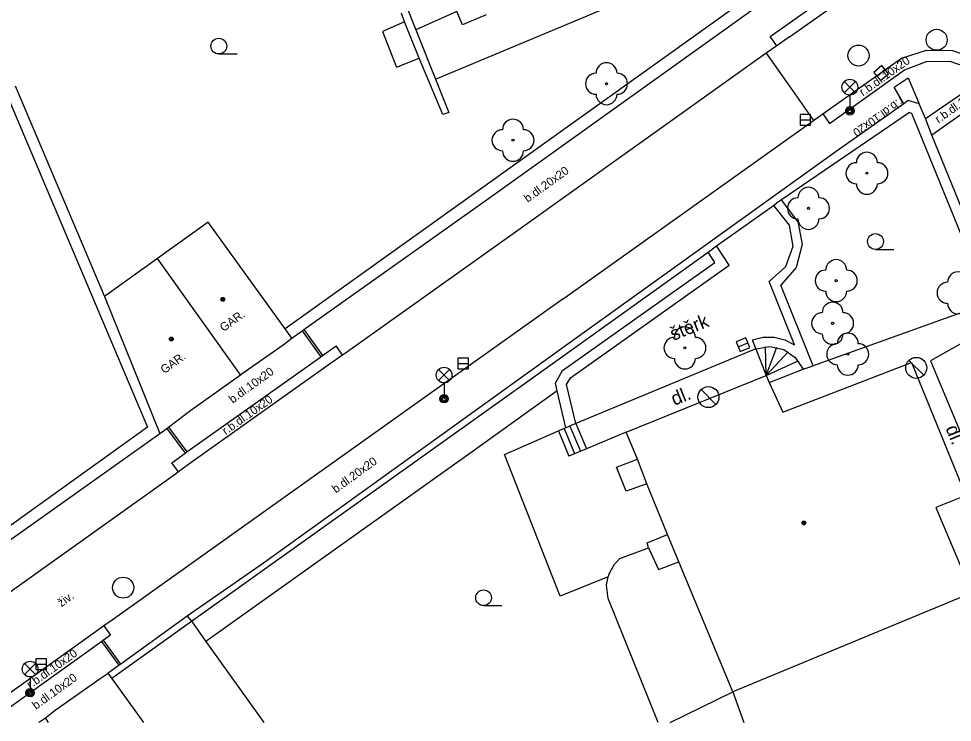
# Model space of a CAD drawing. Extents: x -600391 to -599491, y -1160176 to -1159402.
# Drawn here: x -599839.54 to -599795.12, y -1160176.08 to -1160142.59 of the extents above; entities that cross this region are included whole.
import ezdxf

# ---------------------------------------------------------------- set-up
doc = ezdxf.new("R2010")
doc.units = 0
for name, color, linetype in [('Level 10', 7, 'Continuous'), ('Level 11', 7, 'Continuous'), ('Level 22', 7, 'Continuous'), ('Level 27', 7, 'Continuous'), ('Level 33', 7, 'Continuous'), ('Level 36', 7, 'Continuous'), ('Level 39', 7, 'Continuous'), ('Level 40', 7, 'Continuous'), ('Level 41', 7, 'Continuous'), ('Level 5', 7, 'Continuous'), ('Level 51', 7, 'Continuous'), ('Level 6', 7, 'Continuous'), ('Level 7', 7, 'Continuous')]:
    doc.layers.add(name, color=color, linetype=linetype)

msp = doc.modelspace()

# ---------------------------------------------------------------- linework, layer by layer
at = {"layer": 'Level 10'}
for points in [[(-599802.86, -1160143.46), (-599798, -1160140.01)], [(-599802.86, -1160143.46), (-599803.47, -1160143.89), (-599803.97, -1160144.24), (-599815.9, -1160152.75), (-599823.99, -1160158.51), (-599824.13, -1160158.61), (-599824.81, -1160159.08), (-599831.29, -1160163.69), (-599831.93, -1160164.16), (-599832.08, -1160164.27), (-599845.83, -1160174.08), (-599846.15, -1160174.3), (-599846.65, -1160174.65), (-599848.652, -1160176.079)], [(-599797.53, -1160144.47), (-599796.35, -1160144.09), (-599795.11, -1160144.11), (-599793.94, -1160144.52)], [(-599813.64, -1160155.93), (-599801.72, -1160147.44), (-599801.28, -1160147.13), (-599797.53, -1160144.47)], [(-599813.64, -1160155.93), (-599829.07, -1160166.92), (-599835.1, -1160171.22), (-599835.49, -1160171.49), (-599835.91, -1160171.79), (-599841.925, -1160176.079)]]:
    msp.add_lwpolyline(points, dxfattribs=at)
at = {"layer": 'Level 11'}
msp.add_line((-599809.113, -1160176.079), (-599811.49, -1160170.18), dxfattribs=at)
for points in [[(-599819.71, -1160145.47), (-599802.47, -1160138.26), (-599804.18, -1160134.3)], [(-599803.78, -1160143.45), (-599798.3, -1160139.56)], [(-599817.3, -1160142.41), (-599818.43, -1160142.88), (-599818.7, -1160142.25), (-599820.65, -1160143.12)], [(-599803.47, -1160143.89), (-599803.78, -1160143.45)], [(-599803.97, -1160144.24), (-599802.83, -1160145.86), (-599801.72, -1160147.44)], [(-599797.39, -1160145.03), (-599796.35, -1160144.64), (-599795.24, -1160144.62), (-599794.19, -1160144.98)], [(-599800.96, -1160147.58), (-599797.39, -1160145.03)], [(-599797.43, -1160146.64), (-599797.88, -1160145.86), (-599797.21, -1160145.41), (-599796.7, -1160146.65)], [(-599796.39, -1160147.35), (-599793.96, -1160145.68), (-599793.34, -1160146.21), (-599796.09, -1160148.13)], [(-599801.28, -1160147.13), (-599800.96, -1160147.58)], [(-599793.38, -1160156.12), (-599801.74, -1160159.11)], [(-599826.05, -1160157.45), (-599825.17, -1160158.69)], [(-599825.97, -1160157.39), (-599825.09, -1160158.63)], [(-599792.97, -1160157.08), (-599796.15, -1160158.88)], [(-599832.25, -1160163.73), (-599831.62, -1160163.27), (-599831.54, -1160163.21), (-599825.17, -1160158.69), (-599825.09, -1160158.63), (-599824.44, -1160158.17)], [(-599824.13, -1160158.61), (-599824.44, -1160158.17)], [(-599804.47, -1160158.3), (-599813.03, -1160161.86), (-599813.5, -1160162.06), (-599813.86, -1160162.21)], [(-599804.47, -1160158.3), (-599803.98, -1160159.57)], [(-599803.98, -1160159.57), (-599804.01, -1160158.2)], [(-599803.98, -1160159.57), (-599803.47, -1160158.23)], [(-599803.98, -1160159.57), (-599802.93, -1160158.45)], [(-599803.98, -1160159.57), (-599802.45, -1160158.87)], [(-599803.83, -1160159.9), (-599802.21, -1160159.28)], [(-599796.15, -1160158.88), (-599793.65, -1160164.87)], [(-599813.03, -1160161.86), (-599812.53, -1160163.06)], [(-599832.5, -1160162.09), (-599831.62, -1160163.27)], [(-599832.42, -1160162.03), (-599831.54, -1160163.21)], [(-599811.49, -1160169.15), (-599813.78, -1160170.07), (-599816.42, -1160163.33), (-599813.86, -1160162.21)], [(-599813.86, -1160162.21), (-599813.36, -1160163.41)], [(-599813.58, -1160162.09), (-599813.09, -1160163.29)], [(-599810.63, -1160162.27), (-599812.53, -1160163.06), (-599813.36, -1160163.41)], [(-599813.31, -1160161.98), (-599812.81, -1160163.18)], [(-599831.93, -1160164.16), (-599832.25, -1160163.73)], [(-599809.65, -1160164.73), (-599810.63, -1160165.08), (-599811.09, -1160163.93), (-599810.09, -1160163.56)], [(-599809.57, -1160167.78), (-599809.64, -1160167.54), (-599808.67, -1160167.14)], [(-599810.93, -1160168.29), (-599809.57, -1160167.78)], [(-599809.57, -1160167.78), (-599809.09, -1160168.8), (-599808.13, -1160168.44)], [(-599811.49, -1160170.18), (-599811.57, -1160169.55), (-599811.49, -1160169.15), (-599811.42, -1160168.95), (-599811.19, -1160168.56), (-599810.93, -1160168.29)], [(-599835.49, -1160171.49), (-599835.18, -1160171.93)], [(-599835.18, -1160171.93), (-599835.5, -1160172.17), (-599835.58, -1160172.23), (-599840.98, -1160176.079)], [(-599834.68, -1160173.31), (-599835.5, -1160172.17)], [(-599834.76, -1160173.36), (-599835.58, -1160172.23)]]:
    msp.add_lwpolyline(points, dxfattribs=at)
at = {"layer": 'Level 22'}
for centre in [(-599811.57, -1160145.69), (-599816.02, -1160148.38), (-599799.18, -1160149.95), (-599801.96, -1160151.62), (-599800.64, -1160155.06), (-599800.81, -1160157.09), (-599807.84, -1160158.26), (-599800.09, -1160158.56)]:
    msp.add_circle(centre, 0.05, dxfattribs=at)
for centre, start, end in [((-599811.57, -1160145.19), 0, 180), ((-599812.07, -1160145.69), 90, 270), ((-599811.07, -1160145.69), 270, 90), ((-599811.57, -1160146.19), 180, 0), ((-599816.02, -1160147.88), 0, 180), ((-599816.52, -1160148.38), 90, 270), ((-599815.52, -1160148.38), 270, 90), ((-599816.02, -1160148.88), 180, 0), ((-599799.18, -1160149.45), 0, 180), ((-599799.68, -1160149.95), 90, 270), ((-599798.68, -1160149.95), 270, 90), ((-599801.96, -1160151.12), 0, 180), ((-599799.18, -1160150.45), 180, 0), ((-599802.46, -1160151.62), 90, 270), ((-599801.46, -1160151.62), 270, 90), ((-599801.96, -1160152.12), 180, 0), ((-599800.64, -1160154.56), 0, 180), ((-599801.14, -1160155.06), 90, 270), ((-599800.14, -1160155.06), 270, 90), ((-599794.84, -1160155.14), 0, 180), ((-599795.34, -1160155.64), 90, 270), ((-599800.64, -1160155.56), 180, 0), ((-599800.81, -1160156.59), 0, 180), ((-599794.84, -1160156.14), 180, 0), ((-599801.31, -1160157.09), 90, 270), ((-599800.31, -1160157.09), 270, 90), ((-599807.84, -1160157.76), 0, 180), ((-599808.34, -1160158.26), 90, 270), ((-599807.34, -1160158.26), 270, 90), ((-599800.81, -1160157.59), 180, 0), ((-599800.09, -1160158.06), 0, 180), ((-599800.59, -1160158.56), 90, 270), ((-599799.59, -1160158.56), 270, 90), ((-599807.84, -1160158.76), 180, 0), ((-599800.09, -1160159.06), 180, 0)]:
    msp.add_arc(centre, 0.5, start, end, dxfattribs=at)
at = {"layer": 'Level 27'}
for p, q in [((-599798.308, -1160145.02), (-599798.692, -1160145.34)), ((-599802.36, -1160147.41), (-599801.86, -1160147.41)), ((-599805.312, -1160158.204), (-599804.848, -1160158.016)), ((-599818.64, -1160159), (-599818.14, -1160159)), ((-599796.477, -1160159.564), (-599797.184, -1160158.857)), ((-599806.367, -1160160.954), (-599807.074, -1160160.247)), ((-599838.72, -1160173.31), (-599838.22, -1160173.31))]:
    msp.add_line(p, q, dxfattribs=at)
for points in [[(-599798.468, -1160144.828), (-599798.852, -1160145.148), (-599798.532, -1160145.532), (-599798.148, -1160145.212)], [(-599802.36, -1160147.66), (-599801.86, -1160147.66), (-599801.86, -1160147.16), (-599802.36, -1160147.16)], [(-599805.218, -1160158.436), (-599804.754, -1160158.248), (-599804.942, -1160157.784), (-599805.406, -1160157.972)], [(-599818.64, -1160159.25), (-599818.14, -1160159.25), (-599818.14, -1160158.75), (-599818.64, -1160158.75)], [(-599838.72, -1160173.56), (-599838.22, -1160173.56), (-599838.22, -1160173.06), (-599838.72, -1160173.06)]]:
    msp.add_lwpolyline(points, close=True, dxfattribs=at)
for centre in [(-599795.86, -1160143.6), (-599799.58, -1160144.35), (-599796.83, -1160159.21), (-599806.72, -1160160.6), (-599834.57, -1160169.67)]:
    msp.add_circle(centre, 0.5, dxfattribs=at)
at = {"layer": 'Level 33'}
for p, q in [((-599800.255, -1160146.12), (-599799.725, -1160145.59)), ((-599800.255, -1160145.59), (-599799.725, -1160146.12)), ((-599799.99, -1160146.23), (-599799.99, -1160146.98)), ((-599819.565, -1160159.82), (-599819.035, -1160159.29)), ((-599819.565, -1160159.29), (-599819.035, -1160159.82)), ((-599819.3, -1160159.93), (-599819.3, -1160160.68)), ((-599839.265, -1160173.81), (-599838.735, -1160173.28)), ((-599839.265, -1160173.28), (-599838.735, -1160173.81)), ((-599839, -1160173.92), (-599839, -1160174.67))]:
    msp.add_line(p, q, dxfattribs=at)
for centre, radius in [((-599799.99, -1160145.855), 0.375), ((-599799.99, -1160146.98), 0.2), ((-599799.99, -1160146.98), 0.145), ((-599799.99, -1160146.98), 0.0876), ((-599819.3, -1160159.555), 0.375), ((-599819.3, -1160160.68), 0.2), ((-599819.3, -1160160.68), 0.145), ((-599819.3, -1160160.68), 0.0876), ((-599839, -1160173.545), 0.375), ((-599839, -1160174.67), 0.2), ((-599839, -1160174.67), 0.145), ((-599839, -1160174.67), 0.0876)]:
    msp.add_circle(centre, radius, dxfattribs=at)
at = {"layer": 'Level 36'}
for p, q in [((-599830.02, -1160144.275), (-599829.145, -1160144.275)), ((-599798.77, -1160153.575), (-599797.895, -1160153.575)), ((-599817.42, -1160170.525), (-599816.545, -1160170.525))]:
    msp.add_line(p, q, dxfattribs=at)
for centre in [(-599830.02, -1160143.9), (-599798.77, -1160153.2), (-599817.42, -1160170.15)]:
    msp.add_circle(centre, 0.375, dxfattribs=at)
at = {"layer": 'Level 39'}
for centre, radius in [((-599829.83, -1160155.95), 0.09), ((-599829.83, -1160155.95), 0.0398), ((-599832.28, -1160157.84), 0.09), ((-599832.28, -1160157.84), 0.0398), ((-599802.18, -1160166.59), 0.09), ((-599802.18, -1160166.59), 0.0398)]:
    msp.add_circle(centre, radius, dxfattribs=at)
at = {"layer": 'Level 5'}
for p, q in [((-599808.543, -1160176.079), (-599805.56, -1160174.63)), ((-599805.56, -1160174.63), (-599805.032, -1160176.079)), ((-599838.116, -1160176.079), (-599838.27, -1160175.86))]:
    msp.add_line(p, q, dxfattribs=at)
for points in [[(-599830.52, -1160152.28), (-599832.93, -1160154.01)], [(-599826.54, -1160157.8), (-599826.86, -1160157.35), (-599830.52, -1160152.28)], [(-599832.93, -1160154.01), (-599835.46, -1160155.82)], [(-599828.98, -1160159.54), (-599832.93, -1160154.01)], [(-599835.46, -1160155.82), (-599832.83, -1160162.33)], [(-599826.96, -1160158.12), (-599826.54, -1160157.8)], [(-599803.18, -1160161.32), (-599797.05, -1160158.95)], [(-599797.05, -1160158.95), (-599794.5, -1160165.22), (-599794.47, -1160165.29)], [(-599829.43, -1160159.86), (-599828.98, -1160159.54)], [(-599828.98, -1160159.54), (-599828.9, -1160159.48)], [(-599810.63, -1160162.27), (-599803.98, -1160159.57)], [(-599803.98, -1160159.57), (-599803.83, -1160159.9), (-599803.18, -1160161.32)], [(-599832.83, -1160162.33), (-599832.5, -1160162.09), (-599832.42, -1160162.03), (-599831.35, -1160161.23)], [(-599810.09, -1160163.56), (-599810.63, -1160162.27)], [(-599809.65, -1160164.73), (-599810.09, -1160163.56)], [(-599808.67, -1160167.14), (-599809.65, -1160164.73)], [(-599794.47, -1160165.29), (-599795.9, -1160165.86)], [(-599795.9, -1160165.86), (-599794.3, -1160169.64), (-599794.18, -1160169.92)], [(-599808.13, -1160168.44), (-599808.67, -1160167.14)], [(-599805.56, -1160174.63), (-599808.13, -1160168.44)], [(-599794.18, -1160169.92), (-599805.56, -1160174.63)], [(-599835.66, -1160173.99), (-599835.28, -1160173.74)], [(-599833.583, -1160176.079), (-599835.11, -1160173.97), (-599835.28, -1160173.74)], [(-599838.27, -1160175.86), (-599837.8, -1160175.5)], [(-599838.55, -1160176.06), (-599838.27, -1160175.86)]]:
    msp.add_lwpolyline(points, dxfattribs=at)
at = {"layer": 'Level 51'}
for points in [[(-599821.11, -1160141.97), (-599820.65, -1160143.12), (-599819.71, -1160145.47), (-599819.07, -1160147.06)], [(-599821.19, -1160142.74), (-599821.33, -1160142.33)], [(-599821.19, -1160142.74), (-599822.23, -1160143.2)], [(-599820.48, -1160144.48), (-599821.19, -1160142.74)], [(-599822.23, -1160143.2), (-599821.57, -1160144.9)], [(-599821.57, -1160144.9), (-599820.48, -1160144.48)], [(-599819.36, -1160147.15), (-599820.48, -1160144.48)], [(-599819.07, -1160147.06), (-599819.36, -1160147.15)]]:
    msp.add_lwpolyline(points, dxfattribs=at)
at = {"layer": 'Level 6'}
msp.add_line((-599838.578, -1160176.079), (-599838.55, -1160176.06), dxfattribs=at)
for points in [[(-599828.9, -1160159.48), (-599826.96, -1160158.12)], [(-599831.35, -1160161.23), (-599829.43, -1160159.86)], [(-599837.8, -1160175.5), (-599835.66, -1160173.99)]]:
    msp.add_lwpolyline(points, dxfattribs=at)
at = {"layer": 'Level 7'}
for points in [[(-599800.63, -1160138.51), (-599800.86, -1160138.74), (-599826.86, -1160157.35)], [(-599817.08, -1160151.08), (-599800.58, -1160139.26)], [(-599839.71, -1160145.79), (-599835.46, -1160155.82)], [(-599840.19, -1160146.03), (-599833.42, -1160162.04), (-599847.39, -1160172.06)], [(-599792.92, -1160155.91), (-599796.09, -1160148.13), (-599796.39, -1160147.35), (-599796.7, -1160146.65), (-599797.22, -1160146.49), (-599797.43, -1160146.64), (-599800.65, -1160148.92), (-599812.5, -1160157.43), (-599827.9, -1160168.5), (-599831.52, -1160171.02)], [(-599797.16, -1160147.06), (-599803.24, -1160151.21), (-599803.48, -1160151.37)], [(-599797.16, -1160147.06), (-599797.06, -1160147.09), (-599793.38, -1160156.12)], [(-599826.54, -1160157.8), (-599826.05, -1160157.45), (-599825.97, -1160157.39), (-599817.08, -1160151.08)], [(-599802.47, -1160152.24), (-599803.24, -1160151.21)], [(-599814.26, -1160159.1), (-599806.74, -1160153.7), (-599806.33, -1160153.41), (-599803.63, -1160151.48), (-599803.48, -1160151.37)], [(-599803.63, -1160151.48), (-599802.88, -1160152.42), (-599802.71, -1160153.44), (-599803.06, -1160154.41), (-599803.83, -1160155.1)], [(-599802.47, -1160152.24), (-599802.26, -1160153.34), (-599802.54, -1160154.43), (-599803.27, -1160155.28)], [(-599813.03, -1160161.86), (-599813.47, -1160160.01), (-599813.29, -1160159.68), (-599805.73, -1160154.33), (-599806.33, -1160153.41)], [(-599813.5, -1160162.06), (-599813.92, -1160160.3), (-599814, -1160159.94), (-599813.67, -1160159.34), (-599806.41, -1160154.2), (-599806.74, -1160153.7)], [(-599802.63, -1160158.11), (-599803.83, -1160155.1)], [(-599801.74, -1160159.11), (-599803.27, -1160155.28)], [(-599804.63, -1160157.88), (-599804.12, -1160157.75), (-599803.6, -1160157.75), (-599803.09, -1160157.87)], [(-599804.47, -1160158.3), (-599804.63, -1160157.88)], [(-599803.09, -1160157.87), (-599802.63, -1160158.11)], [(-599804.47, -1160158.3), (-599803.8, -1160158.19), (-599803.14, -1160158.33), (-599802.59, -1160158.72)], [(-599802.59, -1160158.72), (-599802.21, -1160159.28)], [(-599831.32, -1160171.27), (-599814.26, -1160159.1)], [(-599802.21, -1160159.28), (-599801.74, -1160159.11)], [(-599813.92, -1160160.3), (-599817.96, -1160163.2), (-599830.63, -1160172.23)], [(-599847.1, -1160172.47), (-599832.83, -1160162.33)], [(-599831.52, -1160171.02), (-599834.68, -1160173.31), (-599834.76, -1160173.36), (-599835.28, -1160173.74)], [(-599835.11, -1160173.97), (-599831.32, -1160171.27)], [(-599831.52, -1160171.02), (-599831.32, -1160171.27)], [(-599831.32, -1160171.27), (-599830.63, -1160172.23), (-599827.874, -1160176.079)]]:
    msp.add_lwpolyline(points, dxfattribs=at)

# ---------------------------------------------------------------- texts
at = {"layer": 'Level 40'}
for s, height, rotation, p in [('r.b.dl.10x20', 0.39997, 35.3645, (-599799.37, -1160146.3)), ('r.b.dl.10x20', 0.4, 35.43, (-599795.77, -1160147.59)), ('r.b.dl.10x20', 0.4, 215, (-599797.6, -1160146.31)), ('b.dl.20x20', 0.4, 35.922, (-599815.32, -1160151.36)), ('štěrk', 0.65, 22, (-599808.39, -1160157.93)), ('b.dl.10x20', 0.4, 35.922, (-599829.36, -1160160.92)), ('dl.', 0.65, 22.0979, (-599808.34, -1160161.02)), ('r.b.dl.10x20', 0.39997, 35.3645, (-599829.69, -1160162.42)), ('dl.', 0.65, 292.095, (-599795.45, -1160162.08)), ('b.dl.20x20', 0.4, 35.922, (-599824.45, -1160165.19)), ('živ.', 0.4, 36.087, (-599837.51, -1160170.61)), ('r.b.dl.10x20', 0.39997, 35.3645, (-599838.99, -1160174.5)), ('b.dl.10x20', 0.4, 35.922, (-599838.72, -1160175.49))]:
    msp.add_text(s, height=height, rotation=rotation, dxfattribs=at).set_placement(p)
at = {"layer": 'Level 41'}
for p in [(-599829.79, -1160157.51), (-599832.61, -1160159.51)]:
    msp.add_text('GAR.', height=0.4, rotation=35.9571, dxfattribs=at).set_placement(p)

doc.saveas('drawing.dxf')
